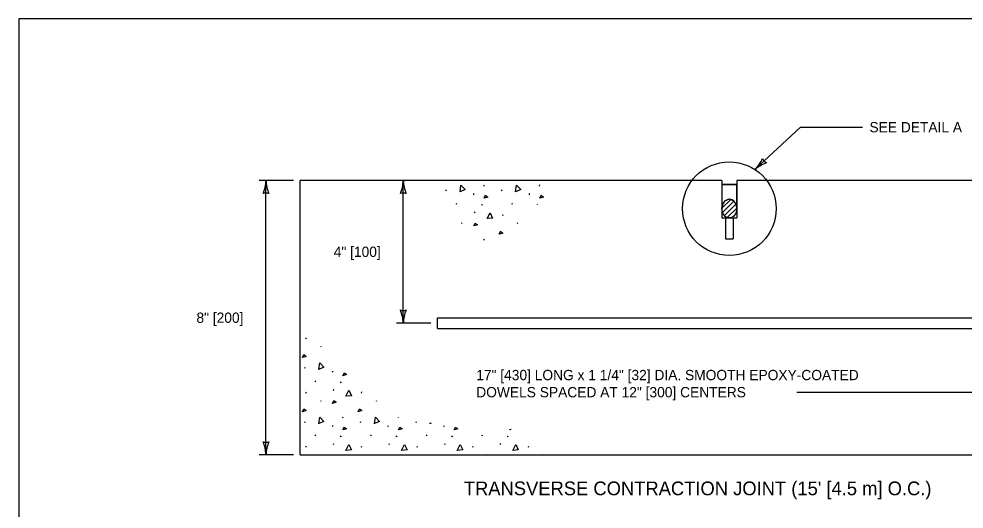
# Model space of a CAD drawing. Extents: x 49991.4 to 50021, y 49987.6 to 50011.4.
# Drawn here: x 50000.34 to 50005.84, y 50008.4 to 50011.26 of the extents above; entities that cross this region are included whole.
import ezdxf

# ---------------------------------------------------------------- set-up
doc = ezdxf.new("R2010")
doc.units = 0
for name, color, linetype in [('Level 1', 7, 'Continuous'), ('Level 2', 7, 'Continuous'), ('Level 3', 7, 'Continuous')]:
    doc.layers.add(name, color=color, linetype=linetype)

msp = doc.modelspace()

# ---------------------------------------------------------------- linework, layer by layer
at = {"layer": 'Level 1'}
for p, q in [((50001.9751, 50008.7199), (50001.9751, 50010.3199)), ((50003.0448, 50010.288), (50003.0475, 50010.2941)), ((50003.3689, 50010.288), (50003.3716, 50010.2941)), ((50004.4317, 50010.3199), (50004.4317, 50010.1014)), ((50004.4317, 50010.2969), (50004.5185, 50010.2969)), ((50004.5185, 50010.3199), (50004.5185, 50010.1014)), ((50002.8235, 50010.2603), (50002.8262, 50010.2664)), ((50002.9844, 50010.2433), (50002.9851, 50010.2372)), ((50003.1477, 50010.2603), (50003.1504, 50010.2664)), ((50003.3085, 50010.2433), (50003.3092, 50010.2372)), ((50002.8851, 50010.1818), (50002.8878, 50010.1879)), ((50003.0306, 50010.1818), (50003.0333, 50010.1777)), ((50003.0333, 50010.1803), (50003.036, 50010.1762)), ((50003.2092, 50010.1818), (50003.2119, 50010.1879)), ((50003.3547, 50010.1818), (50003.3554, 50010.1807)), ((50004.4318, 50010.1578), (50004.4833, 50010.2093)), ((50004.4357, 50010.1334), (50004.5014, 50010.1991)), ((50004.446, 50010.1155), (50004.513, 50010.1824)), ((50002.9907, 50010.1316), (50002.9934, 50010.1377)), ((50003.1544, 50010.1161), (50003.1571, 50010.1222)), ((50004.4626, 50010.1038), (50004.5183, 50010.1595)), ((50004.4941, 50010.107), (50004.5088, 50010.1216)), ((50002.9149, 50010.0728), (50002.9176, 50010.0687)), ((50003.239, 50010.0728), (50003.2417, 50010.0687)), ((50004.4317, 50010.1014), (50004.5185, 50010.1014)), ((50004.452, 50010.1014), (50004.452, 50009.9803)), ((50004.4982, 50010.1014), (50004.4982, 50009.9803)), ((50003.0448, 50009.972), (50003.0475, 50009.978)), ((50004.452, 50009.9803), (50004.4982, 50009.9803)), ((50002.7751, 50009.4574), (50002.7751, 50009.5199)), ((50002.0078, 50009.3966), (50002.0105, 50009.4027)), ((50002.0924, 50009.3533), (50002.0951, 50009.3492)), ((50002.001, 50009.2247), (50002.0037, 50009.2308)), ((50002.1619, 50009.2077), (50002.1626, 50009.2016)), ((50002.0626, 50009.1462), (50002.0653, 50009.1523)), ((50002.2081, 50009.1462), (50002.2108, 50009.1422)), ((50002.2108, 50009.1447), (50002.2135, 50009.1406)), ((50002.0078, 50009.0805), (50002.0105, 50009.0866)), ((50002.1682, 50009.0961), (50002.1709, 50009.1021)), ((50002.3319, 50009.0805), (50002.3346, 50009.0866)), ((50002.0924, 50009.0372), (50002.0951, 50009.0331)), ((50002.4165, 50009.0372), (50002.4192, 50009.0331)), ((50002.001, 50008.9086), (50002.0037, 50008.9147)), ((50002.2223, 50008.9364), (50002.225, 50008.9425)), ((50002.3252, 50008.9086), (50002.3279, 50008.9147)), ((50002.5464, 50008.9364), (50002.5469, 50008.9373)), ((50002.6493, 50008.9086), (50002.652, 50008.9147)), ((50002.1619, 50008.8916), (50002.1626, 50008.8855)), ((50002.486, 50008.8916), (50002.4867, 50008.8855)), ((50002.8102, 50008.8916), (50002.8109, 50008.8855)), ((50002.0626, 50008.8301), (50002.0653, 50008.8362)), ((50002.2081, 50008.8301), (50002.2108, 50008.8261)), ((50002.2108, 50008.8286), (50002.2135, 50008.8245)), ((50002.3867, 50008.8301), (50002.3894, 50008.8362)), ((50002.5322, 50008.8301), (50002.5349, 50008.8261)), ((50002.5349, 50008.8286), (50002.5376, 50008.8245)), ((50002.7109, 50008.8301), (50002.7136, 50008.8362)), ((50002.8564, 50008.8301), (50002.8591, 50008.8261)), ((50002.8591, 50008.8286), (50002.8618, 50008.8245)), ((50003.035, 50008.8301), (50003.0377, 50008.8362)), ((50003.1805, 50008.8301), (50003.1832, 50008.8261)), ((50003.1832, 50008.8286), (50003.1859, 50008.8245)), ((50002.0078, 50008.7644), (50002.0105, 50008.7705)), ((50002.1682, 50008.78), (50002.1709, 50008.7861)), ((50002.3319, 50008.7644), (50002.3346, 50008.7705)), ((50002.4923, 50008.78), (50002.495, 50008.7861)), ((50002.6561, 50008.7644), (50002.6588, 50008.7705)), ((50002.8164, 50008.78), (50002.8191, 50008.7861)), ((50002.9802, 50008.7644), (50002.9829, 50008.7705)), ((50003.1406, 50008.78), (50003.1433, 50008.7861)), ((50003.3043, 50008.7644), (50003.3071, 50008.7705)), ((50002.0924, 50008.7211), (50002.0932, 50008.7199)), ((50002.4165, 50008.7211), (50002.4173, 50008.7199)), ((50002.7407, 50008.7211), (50002.7414, 50008.7199)), ((50003.0648, 50008.7211), (50003.0656, 50008.7199)), ((50003.3889, 50008.7211), (50003.3897, 50008.7199))]:
    msp.add_line(p, q, dxfattribs=at)
msp.add_lwpolyline([(50008.6146, 50011.2628), (50000.3356, 50011.2628), (50000.3356, 50000.0624), (50008.6146, 50000.0624)], close=True, dxfattribs=at)
for points in [[(50001.9751, 50008.7199), (50006.9751, 50008.7199), (50006.9751, 50010.3199), (50004.5185, 50010.3199)], [(50004.4317, 50010.3199), (50001.9751, 50010.3199)], [(50002.9058, 50010.2533), (50002.9112, 50010.292), (50002.9354, 50010.2669), (50002.9065, 50010.2535)], [(50003.23, 50010.2533), (50003.2353, 50010.292), (50003.2596, 50010.2669), (50003.2306, 50010.2535)], [(50004.5184, 50010.1595), (50004.5185, 50010.1595), (50004.5185, 50010.2969), (50004.4317, 50010.2969), (50004.4317, 50010.1578), (50004.4317, 50010.1578)], [(50003.0462, 50010.217), (50003.0543, 50010.2339), (50003.0678, 50010.2238), (50003.0462, 50010.217)], [(50003.3703, 50010.217), (50003.3784, 50010.2339), (50003.3919, 50010.2238), (50003.3703, 50010.217)], [(50003.0631, 50010.0978), (50003.0813, 50010.1323), (50003.0955, 50010.1005), (50003.0637, 50010.0978)], [(50002.9859, 50010.0552), (50002.994, 50010.0721), (50003.0076, 50010.062), (50002.9859, 50010.0552)], [(50003.1343, 50010.0068), (50003.1424, 50010.0237), (50003.1559, 50010.0136), (50003.1343, 50010.0068)], [(50002.7751, 50009.5199), (50006.1751, 50009.5199), (50006.1751, 50009.4574)], [(50002.7751, 50009.4574), (50006.1751, 50009.4574)], [(50001.9876, 50009.2873), (50001.9957, 50009.3042), (50002.0093, 50009.2941), (50001.9876, 50009.2873)], [(50002.0834, 50009.2177), (50002.0887, 50009.2564), (50002.1129, 50009.2314), (50002.084, 50009.2179)], [(50002.2237, 50009.1814), (50002.2318, 50009.1983), (50002.2453, 50009.1882), (50002.2237, 50009.1814)], [(50002.2406, 50009.0622), (50002.2589, 50009.0967), (50002.2731, 50009.0649), (50002.2413, 50009.0622)], [(50002.1634, 50009.0196), (50002.1715, 50009.0365), (50002.1851, 50009.0264), (50002.1634, 50009.0196)], [(50001.9876, 50008.9712), (50001.9957, 50008.9881), (50002.0093, 50008.978), (50001.9876, 50008.9712)], [(50002.3118, 50008.9712), (50002.3199, 50008.9881), (50002.3334, 50008.978), (50002.3118, 50008.9712)], [(50002.0834, 50008.9016), (50002.0887, 50008.9403), (50002.1129, 50008.9153), (50002.084, 50008.9018)], [(50002.4075, 50008.9016), (50002.4129, 50008.9403), (50002.4371, 50008.9153), (50002.4081, 50008.9018)], [(50002.7316, 50008.9016), (50002.7322, 50008.9058)], [(50002.7384, 50008.9047), (50002.7323, 50008.9018)], [(50002.2237, 50008.8653), (50002.2318, 50008.8822), (50002.2453, 50008.8721), (50002.2237, 50008.8653)], [(50002.5478, 50008.8653), (50002.5559, 50008.8822), (50002.5695, 50008.8721), (50002.5478, 50008.8653)], [(50002.8719, 50008.8653), (50002.8801, 50008.8822), (50002.8936, 50008.8721), (50002.8719, 50008.8653)], [(50003.1961, 50008.8653), (50003.1979, 50008.8691)], [(50003.2038, 50008.8677), (50003.1961, 50008.8653)], [(50002.2406, 50008.7461), (50002.2589, 50008.7806), (50002.2731, 50008.7488), (50002.2413, 50008.7461)], [(50002.5647, 50008.7461), (50002.583, 50008.7806), (50002.5972, 50008.7488), (50002.5654, 50008.7461)], [(50002.8889, 50008.7461), (50002.9071, 50008.7806), (50002.9213, 50008.7488), (50002.8895, 50008.7461)], [(50003.213, 50008.7461), (50003.2313, 50008.7806), (50003.2455, 50008.7488), (50003.2137, 50008.7461)], [(50002.1713, 50008.7199), (50002.1715, 50008.7204), (50002.1722, 50008.7199)], [(50002.4955, 50008.7199), (50002.4957, 50008.7204), (50002.4963, 50008.7199)], [(50002.8196, 50008.7199), (50002.8198, 50008.7204), (50002.8205, 50008.7199)], [(50003.1437, 50008.7199), (50003.144, 50008.7204), (50003.1446, 50008.7199)]]:
    msp.add_lwpolyline(points, dxfattribs=at)
msp.add_ellipse((50004.4751, 50010.1559), major_axis=(0, -0.0545), ratio=0.796445, dxfattribs=at)
for start_param, end_param in [(3.141593, 4.677812), (1.636616, 3.141593)]:
    msp.add_ellipse((50004.4751, 50010.1559), major_axis=(0, -0.0545), ratio=0.796445, start_param=start_param, end_param=end_param, dxfattribs=at)
at = {"layer": 'Level 3'}
for p, q in [((50004.6243, 50010.3839), (50004.8891, 50010.631)), ((50004.8891, 50010.631), (50005.2513, 50010.631)), ((50001.9351, 50010.3199), (50001.7351, 50010.3199)), ((50001.7751, 50008.7199), (50001.7751, 50010.3199)), ((50002.5751, 50009.4887), (50002.5751, 50010.3199)), ((50002.7351, 50009.4887), (50002.5351, 50009.4887)), ((50004.8675, 50009.0854), (50006.0445, 50009.0854)), ((50001.9351, 50008.7199), (50001.7351, 50008.7199))]:
    msp.add_line(p, q, dxfattribs=at)
msp.add_circle((50004.4751, 50010.1559), 0.2724, dxfattribs=at)
for centre, radius, start, end in [((50004.4571, 50010.5461), 0.233, 315.8531, 335.103), ((50004.4571, 50010.5461), 0.233, 315.8531, 335.103), ((50004.718, 50010.4713), 0.0548, 205.1646, 240.887), ((50004.718, 50010.4713), 0.0548, 205.1646, 240.887), ((50004.7692, 50010.2152), 0.2223, 110.4818, 130.6653), ((50004.7692, 50010.2152), 0.2223, 110.4818, 130.6653), ((50001.553, 50010.3291), 0.2223, 337.456, 357.6395), ((50001.553, 50010.3291), 0.2223, 337.456, 357.6395), ((50002.0078, 50010.3314), 0.233, 182.8273, 202.0772), ((50002.0078, 50010.3314), 0.233, 182.8273, 202.0772), ((50002.353, 50010.3291), 0.2223, 337.456, 357.6395), ((50002.353, 50010.3291), 0.2223, 337.456, 357.6395), ((50002.8078, 50010.3314), 0.233, 182.8273, 202.0772), ((50002.8078, 50010.3314), 0.233, 182.8273, 202.0772), ((50001.7751, 50010.1917), 0.0548, 72.1388, 107.8612), ((50001.7751, 50010.1917), 0.0548, 72.1388, 107.8612), ((50002.5751, 50010.1917), 0.0548, 72.1388, 107.8612), ((50002.5751, 50010.1917), 0.0548, 72.1388, 107.8612), ((50002.5751, 50009.6169), 0.0548, 252.1388, 287.8612), ((50002.3424, 50009.4772), 0.233, 2.8273, 22.0772), ((50002.5751, 50009.6169), 0.0548, 252.1388, 287.8612), ((50002.3424, 50009.4772), 0.233, 2.8273, 22.0772), ((50002.7972, 50009.4795), 0.2223, 157.456, 177.6395), ((50002.7972, 50009.4795), 0.2223, 157.456, 177.6395), ((50001.7751, 50008.8482), 0.0548, 252.1388, 287.8612), ((50001.5424, 50008.7084), 0.233, 2.8273, 22.0772), ((50001.7751, 50008.8482), 0.0548, 252.1388, 287.8612), ((50001.5424, 50008.7084), 0.233, 2.8273, 22.0772), ((50001.9972, 50008.7108), 0.2223, 157.456, 177.6395), ((50001.9972, 50008.7108), 0.2223, 157.456, 177.6395)]:
    msp.add_arc(centre, radius, start, end, dxfattribs=at)

# ---------------------------------------------------------------- texts
at = {"layer": 'Level 2'}
for s, height, p in [('SEE DETAIL A', 0.06, (50005.2913, 50010.601)), ('4" [100]', 0.06, (50002.1701, 50009.8743)), ('8" [200]', 0.06, (50001.3701, 50009.4899)), ('17" [430] LONG x 1 1/4" [32] DIA. SMOOTH EPOXY-COATED', 0.06, (50003.0003, 50009.1554)), ('DOWELS SPACED AT 12" [300] CENTERS', 0.06, (50003.0003, 50009.0554)), ("TRANSVERSE CONTRACTION JOINT (15' [4.5 m] O.C.)", 0.08, (50002.9279, 50008.4843))]:
    msp.add_text(s, height=height, dxfattribs=at).set_placement(p)

doc.saveas('drawing.dxf')
